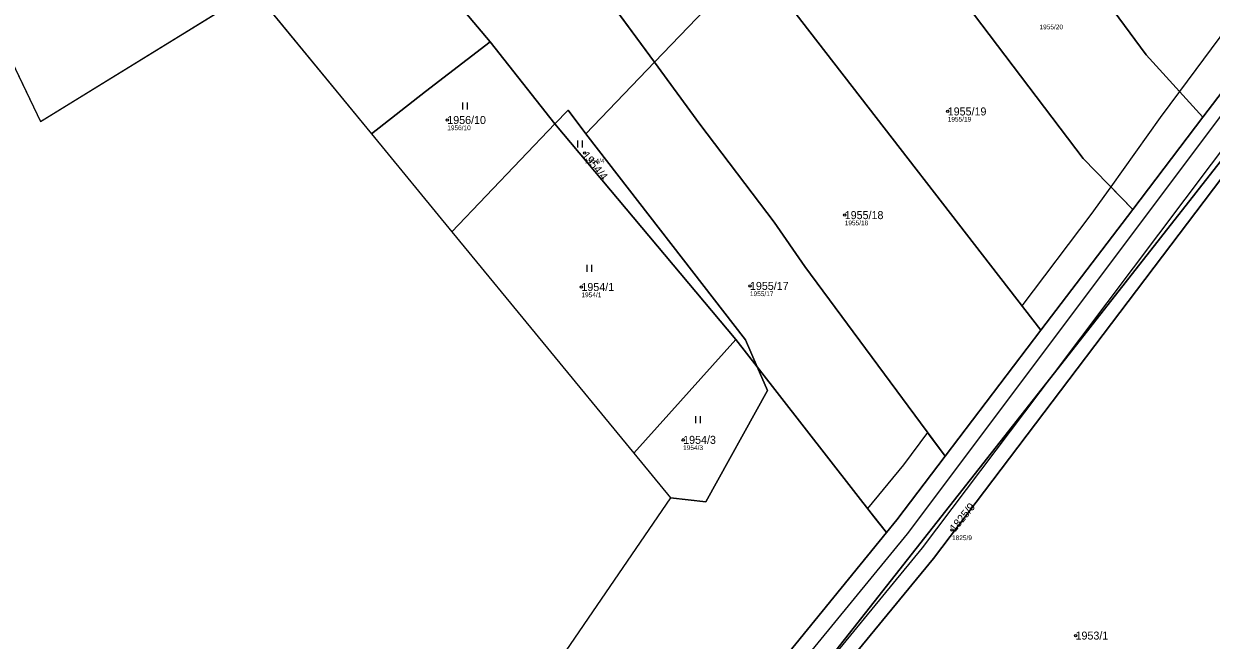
# Model space of a CAD drawing. Extents: x -762274 to -759271, y -1061928 to -1059060.
# Drawn here: x -761526.6 to -761274.4, y -1060728.9 to -1060598 of the extents above; entities that cross this region are included whole.
import ezdxf

# ---------------------------------------------------------------- set-up
doc = ezdxf.new("R2010")
doc.units = 0
for name, color, linetype in [('Definiční body', 7, 'Continuous'), ('Hranice parcel', 7, 'Continuous'), ('Parcelní čísla', 7, 'Continuous'), ('Polygon ku', 7, 'Continuous'), ('Polygon parcely', 7, 'Continuous'), ('Vnitřní kresba', 7, 'Continuous'), ('Věcná břemena k části', 7, 'Continuous'), ('Značky kultur', 7, 'Continuous')]:
    doc.layers.add(name, color=color, linetype=linetype)

msp = doc.modelspace()

# ---------------------------------------------------------------- linework, layer by layer
at = {"layer": 'Definiční body'}
for centre in [(-761436.64, -1060618.46), (-761330.36, -1060616.64), (-761407.45, -1060625.47), (-761352.23, -1060638.65), (-761408.15, -1060653.91), (-761372.36, -1060653.68), (-761386.54, -1060686.35), (-761329.44, -1060705.48), (-761303.21, -1060727.9)]:
    msp.add_circle(centre, 0.25, dxfattribs=at)
at = {"layer": 'Hranice parcel'}
for p, q in [((-761588.44, -1060482.32), (-761523.76, -1060617.27)), ((-761392.63, -1060606.18), (-761436.24, -1060546.87)), ((-761523, -1060618.75), (-761477.78, -1060590.89)), ((-761477.78, -1060590.89), (-761452.75, -1060621.37)), ((-761413.8, -1060619.29), (-761427.51, -1060601.89)), ((-761392.63, -1060606.18), (-761407.19, -1060621.37)), ((-761523.76, -1060617.27), (-761523, -1060618.75)), ((-761276.17, -1060617.86), (-761291.07, -1060637.45)), ((-761413.8, -1060619.29), (-761435.65, -1060642.18)), ((-761375.38, -1060665.02), (-761413.8, -1060619.29)), ((-761452.75, -1060621.37), (-761435.65, -1060642.18)), ((-761291.07, -1060637.45), (-761310.57, -1060663.1)), ((-761435.65, -1060642.18), (-761397.03, -1060689.2)), ((-761310.57, -1060663.1), (-761330.89, -1060689.83)), ((-761375.38, -1060665.02), (-761397.03, -1060689.2)), ((-761370.83, -1060670.85), (-761375.38, -1060665.02)), ((-761397.03, -1060689.2), (-761389.24, -1060698.69)), ((-761423.49, -1060804.37), (-761343.38, -1060706.05))]:
    msp.add_line(p, q, dxfattribs=at)
for points in [[(-761276.17, -1060617.86), (-761288.21, -1060604.6), (-761320.85, -1060560.37), (-761334.27, -1060542.22)], [(-761291.07, -1060637.45), (-761301.57, -1060626.62), (-761326.45, -1060593.88), (-761350.76, -1060560.62)], [(-761427.51, -1060601.89), (-761440.98, -1060585.86), (-761452.51, -1060571.84)], [(-761371.7, -1060584), (-761376.48, -1060589.33), (-761392.63, -1060606.18)], [(-761310.57, -1060663.1), (-761361.34, -1060597.55), (-761371.7, -1060584)], [(-761260.39, -1060596.89), (-761263.67, -1060601.42), (-761276.17, -1060617.86)], [(-761452.75, -1060621.37), (-761441.29, -1060612.4), (-761427.51, -1060601.89)], [(-761330.89, -1060689.83), (-761360.72, -1060649.59), (-761367.23, -1060640.12), (-761382.97, -1060619.31), (-761392.63, -1060606.18)], [(-761407.19, -1060621.37), (-761410.99, -1060616.34), (-761413.8, -1060619.29)], [(-761370.83, -1060670.85), (-761373.31, -1060665.14), (-761407.19, -1060621.37)], [(-761366.94, -1060747.37), (-761363.82, -1060743.41), (-761307.7, -1060672.11), (-761270.13, -1060624.38)], [(-761268.62, -1060626.09), (-761333.35, -1060711.53), (-761364.51, -1060749.36)], [(-761389.24, -1060698.69), (-761381.76, -1060699.54), (-761368.66, -1060675.86), (-761370.83, -1060670.85)], [(-761343.38, -1060706.05), (-761345.61, -1060703.19), (-761370.83, -1060670.85)], [(-761330.89, -1060689.83), (-761341.18, -1060703.36), (-761343.38, -1060706.05)], [(-761389.24, -1060698.69), (-761426.21, -1060752.67), (-761440.81, -1060783.15), (-761452.43, -1060825.93)]]:
    msp.add_lwpolyline(points, dxfattribs=at)
at = {"layer": 'Polygon ku'}
msp.add_lwpolyline([(-761842.98, -1060551.47), (-761837.25, -1060550.74), (-761825.78, -1060549.27), (-761803.29, -1060543.28), (-761774.98, -1060535.73), (-761709.41, -1060525.13), (-761690.07, -1060520.8), (-761668.95, -1060513.73), (-761597.93, -1060485.6), (-761588.44, -1060482.32), (-761523.76, -1060617.27), (-761523, -1060618.75), (-761477.78, -1060590.89), (-761452.75, -1060621.37), (-761435.65, -1060642.18), (-761397.03, -1060689.2), (-761389.24, -1060698.69), (-761426.21, -1060752.67)], dxfattribs=at)
at = {"layer": 'Polygon parcely'}
for points in [[(-761363.82, -1060743.41), (-761307.7, -1060672.11), (-761270.13, -1060624.38), (-761254.54, -1060604.57), (-761221.3, -1060557.24), (-761204.37, -1060534.87), (-761188.29, -1060513.56), (-761163.18, -1060480.02), (-761161.72, -1060481.64), (-761144, -1060458.62), (-761130.15, -1060443.54), (-761110.46, -1060425.39), (-761067.22, -1060396.92), (-761063.63, -1060394.39), (-761043.24, -1060380.01), (-761031.8, -1060369.97), (-761017.49, -1060353.26)], [(-761263.67, -1060601.42), (-761276.17, -1060617.86), (-761291.07, -1060637.45), (-761310.57, -1060663.1), (-761330.89, -1060689.83), (-761341.18, -1060703.36), (-761343.38, -1060706.05), (-761423.49, -1060804.37)]]:
    msp.add_lwpolyline(points, dxfattribs=at)
for points in [[(-761538.1, -1060464.41), (-761588.44, -1060482.32), (-761523.76, -1060617.27), (-761523, -1060618.75), (-761477.78, -1060590.89), (-761493.84, -1060556.2), (-761511.02, -1060524.76)], [(-761307.05, -1060514.14), (-761318.62, -1060524.75), (-761334.27, -1060542.22), (-761320.85, -1060560.37), (-761288.21, -1060604.6), (-761276.17, -1060617.86), (-761263.67, -1060601.42), (-761260.39, -1060596.89), (-761265.28, -1060590.77), (-761276.2, -1060577.12), (-761298.01, -1060532.54)], [(-761407.62, -1060537.03), (-761416.86, -1060524.35), (-761418.28, -1060525.85), (-761436.24, -1060546.87), (-761392.63, -1060606.18), (-761376.48, -1060589.33), (-761371.7, -1060584)], [(-761288.21, -1060604.6), (-761320.85, -1060560.37), (-761334.27, -1060542.22), (-761350.76, -1060560.62), (-761326.45, -1060593.88), (-761301.57, -1060626.62), (-761291.07, -1060637.45), (-761276.17, -1060617.86)], [(-761392.63, -1060606.18), (-761436.24, -1060546.87), (-761453.44, -1060567.01), (-761454.77, -1060568.31), (-761452.51, -1060571.84), (-761440.98, -1060585.86), (-761427.51, -1060601.89), (-761413.8, -1060619.29), (-761410.99, -1060616.34), (-761407.19, -1060621.37)], [(-761301.57, -1060626.62), (-761326.45, -1060593.88), (-761350.76, -1060560.62), (-761371.7, -1060584), (-761361.34, -1060597.55), (-761310.57, -1060663.1), (-761291.07, -1060637.45)], [(-761427.51, -1060601.89), (-761440.98, -1060585.86), (-761452.51, -1060571.84), (-761462.59, -1060580.67), (-761477.78, -1060590.89), (-761452.75, -1060621.37), (-761441.29, -1060612.4)], [(-761310.57, -1060663.1), (-761361.34, -1060597.55), (-761371.7, -1060584), (-761376.48, -1060589.33), (-761392.63, -1060606.18), (-761382.97, -1060619.31), (-761367.23, -1060640.12), (-761360.72, -1060649.59), (-761330.89, -1060689.83)], [(-761435.65, -1060642.18), (-761413.8, -1060619.29), (-761427.51, -1060601.89), (-761441.29, -1060612.4), (-761452.75, -1060621.37)], [(-761360.72, -1060649.59), (-761367.23, -1060640.12), (-761382.97, -1060619.31), (-761392.63, -1060606.18), (-761407.19, -1060621.37), (-761373.31, -1060665.14), (-761370.83, -1060670.85), (-761345.61, -1060703.19), (-761343.38, -1060706.05), (-761341.18, -1060703.36), (-761330.89, -1060689.83)], [(-761413.8, -1060619.29), (-761375.38, -1060665.02), (-761370.83, -1060670.85), (-761373.31, -1060665.14), (-761407.19, -1060621.37), (-761410.99, -1060616.34)], [(-761397.03, -1060689.2), (-761375.38, -1060665.02), (-761413.8, -1060619.29), (-761435.65, -1060642.18)], [(-761268.62, -1060626.09), (-761270.13, -1060624.38), (-761307.7, -1060672.11), (-761363.82, -1060743.41), (-761366.94, -1060747.37), (-761364.51, -1060749.36), (-761333.35, -1060711.53)], [(-761261.47, -1060634.17), (-761268.62, -1060626.09), (-761333.35, -1060711.53), (-761364.51, -1060749.36), (-761306.96, -1060796.48), (-761300.33, -1060786.52), (-761290.49, -1060780.8), (-761275.58, -1060760.1), (-761267.53, -1060762.74), (-761256.19, -1060735.55), (-761217.1, -1060693.41), (-761221.44, -1060691.82), (-761240.65, -1060679.96), (-761229.58, -1060659.37), (-761237.29, -1060653.65), (-761241.79, -1060652.49)], [(-761389.24, -1060698.69), (-761381.76, -1060699.54), (-761368.66, -1060675.86), (-761370.83, -1060670.85), (-761375.38, -1060665.02), (-761397.03, -1060689.2)], [(-761426.21, -1060752.67), (-761440.81, -1060783.15), (-761452.43, -1060825.93), (-761463.01, -1060848.31), (-761423.49, -1060804.37), (-761343.38, -1060706.05), (-761345.61, -1060703.19), (-761370.83, -1060670.85), (-761368.66, -1060675.86), (-761381.76, -1060699.54), (-761389.24, -1060698.69)]]:
    msp.add_lwpolyline(points, close=True, dxfattribs=at)
at = {"layer": 'Vnitřní kresba'}
for p, q in [((-761338.89, -1060706.29), (-761261.87, -1060603.6)), ((-761307.7, -1060672.11), (-761259.11, -1060607.56)), ((-761335.68, -1060709.28), (-761307.7, -1060672.11)), ((-761421.59, -1060807.1), (-761338.89, -1060706.29)), ((-761363.82, -1060743.41), (-761335.68, -1060709.28))]:
    msp.add_line(p, q, dxfattribs=at)
at = {"layer": 'Věcná břemena k části'}
for points in [[(-761281.14, -1060612.39), (-761276.17, -1060617.86), (-761263.67, -1060601.42), (-761260.39, -1060596.89), (-761265.28, -1060590.77), (-761265.85, -1060591.73)], [(-761295.75, -1060632.62), (-761291.07, -1060637.45), (-761276.17, -1060617.86), (-761281.14, -1060612.39), (-761285.25, -1060617.94)], [(-761314.61, -1060657.88), (-761310.57, -1060663.1), (-761291.07, -1060637.45), (-761295.75, -1060632.62), (-761299.95, -1060638.49)], [(-761330.89, -1060689.83), (-761334.65, -1060684.76), (-761339.75, -1060691.64), (-761347.36, -1060700.95), (-761343.38, -1060706.05), (-761341.18, -1060703.36)]]:
    msp.add_lwpolyline(points, close=True, dxfattribs=at)
at = {"layer": 'Značky kultur'}
for p, q in [((-761433.36, -1060616.26), (-761433.36, -1060614.76)), ((-761432.36, -1060616.26), (-761432.36, -1060614.76)), ((-761408.9, -1060624.31), (-761408.9, -1060622.81)), ((-761407.9, -1060624.31), (-761407.9, -1060622.81)), ((-761406.91, -1060650.7), (-761406.91, -1060649.2)), ((-761405.91, -1060650.7), (-761405.91, -1060649.2)), ((-761383.83, -1060682.84), (-761383.83, -1060681.34)), ((-761382.83, -1060682.84), (-761382.83, -1060681.34))]:
    msp.add_line(p, q, dxfattribs=at)

# ---------------------------------------------------------------- texts
at = {"layer": 'Definiční body'}
for s, p in [('1955/20', (-761310.86, -1060599.2)), ('1955/19', (-761330.36, -1060618.8)), ('1956/10', (-761436.64, -1060620.62)), ('1954/4', (-761407.45, -1060627.63)), ('1955/18', (-761352.23, -1060640.81)), ('1954/1', (-761408.15, -1060656.07)), ('1955/17', (-761372.36, -1060655.84)), ('1954/3', (-761386.54, -1060688.51)), ('1825/9', (-761329.44, -1060707.64))]:
    msp.add_text(s, height=1, dxfattribs=at).set_placement(p)
at = {"layer": 'Parcelní čísla'}
for s, p in [('1955/19', (-761330.36, -1060617.49)), ('1956/10', (-761436.64, -1060619.31)), ('1955/18', (-761352.23, -1060639.5)), ('1954/1', (-761408.15, -1060654.76)), ('1955/17', (-761372.36, -1060654.53)), ('1954/3', (-761386.54, -1060687.2)), ('1953/1', (-761303.21, -1060728.75))]:
    msp.add_text(s, height=1.7, dxfattribs=at).set_placement(p)
for s, rotation, p in [('1954/4', 309, (-761408.11, -1060626)), ('1825/9', 51, (-761328.78, -1060706.01))]:
    msp.add_text(s, height=1.7, rotation=rotation, dxfattribs=at).set_placement(p)

doc.saveas('drawing.dxf')
